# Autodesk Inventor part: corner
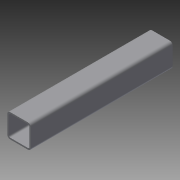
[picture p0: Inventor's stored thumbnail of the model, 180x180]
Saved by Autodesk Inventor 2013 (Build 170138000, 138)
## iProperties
Created: 2008-04
Part Number: corner
Document SubType Name: Modeling
Designer: Jayson Martinez
Density: 1 g/cm^3
Material: Generic
Author: Jayson Martinez
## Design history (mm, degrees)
sketch "Sketch1"
  geometry: L1 (6.35, 0)-(44.45, 0); L2 (50.8, 6.35)-(50.8, 44.45); L3 (44.45, 50.8)-(6.35, 50.8); L4 (0, 44.45)-(0, 6.35); L5 (3.175, 6.35)-(3.175, 44.45); L6 (6.35, 47.625)-(44.45, 47.625); L7 (47.625, 44.45)-(47.625, 6.35); L8 (44.45, 3.175)-(6.35, 3.175); A1 r 6.35 centre (6.35, 44.45) between (6.35, 50.8) and (0, 44.45); A2 r 6.35 centre (6.35, 6.35) between (0, 6.35) and (6.35, 0); A3 r 6.35 centre (44.45, 6.35) between (44.45, 0) and (50.8, 6.35); A4 r 6.35 centre (44.45, 44.45) between (50.8, 44.45) and (44.45, 50.8); A5 r 3.175 centre (6.35, 44.45) between (6.35, 47.625) and (3.175, 44.45); A6 r 3.175 centre (44.45, 44.45) between (47.625, 44.45) and (44.45, 47.625); A7 r 3.175 centre (44.45, 6.35) between (44.45, 3.175) and (47.625, 6.35); A8 r 3.175 centre (6.35, 6.35) between (3.175, 6.35) and (6.35, 3.175); 3 further points
  constraints: 16 end point, 16 point on circle, 8 centre point, 8 tangent, 6 point on line, 4 parallel, 3 equal radius, 2 perpendicular, 1 horizontal, 7 other
  dimensions: "d0" = 50.8 distance of point (0, 0) point (50.8, 0) (= MemberWidth); "d1" = 50.8 distance of point (0, 50.8) point (0, 0) (= MemberWidth); "d2" = 6.35 radius of A1 (= 2 x MemberThickness); "d3" = 3.175 distance between parallel lines of L4 L5 (= MemberThickness)
extrude "Extrusion1" new body sketch "Sketch1" distance "d4" = 304.8 (= CornerLength); taper "d5" = 0 deg
body "Solid1"
other parameters: "MemberThickness" = 3.175, "MemberWidth" = 50.8, "CornerLength" = 304.8
